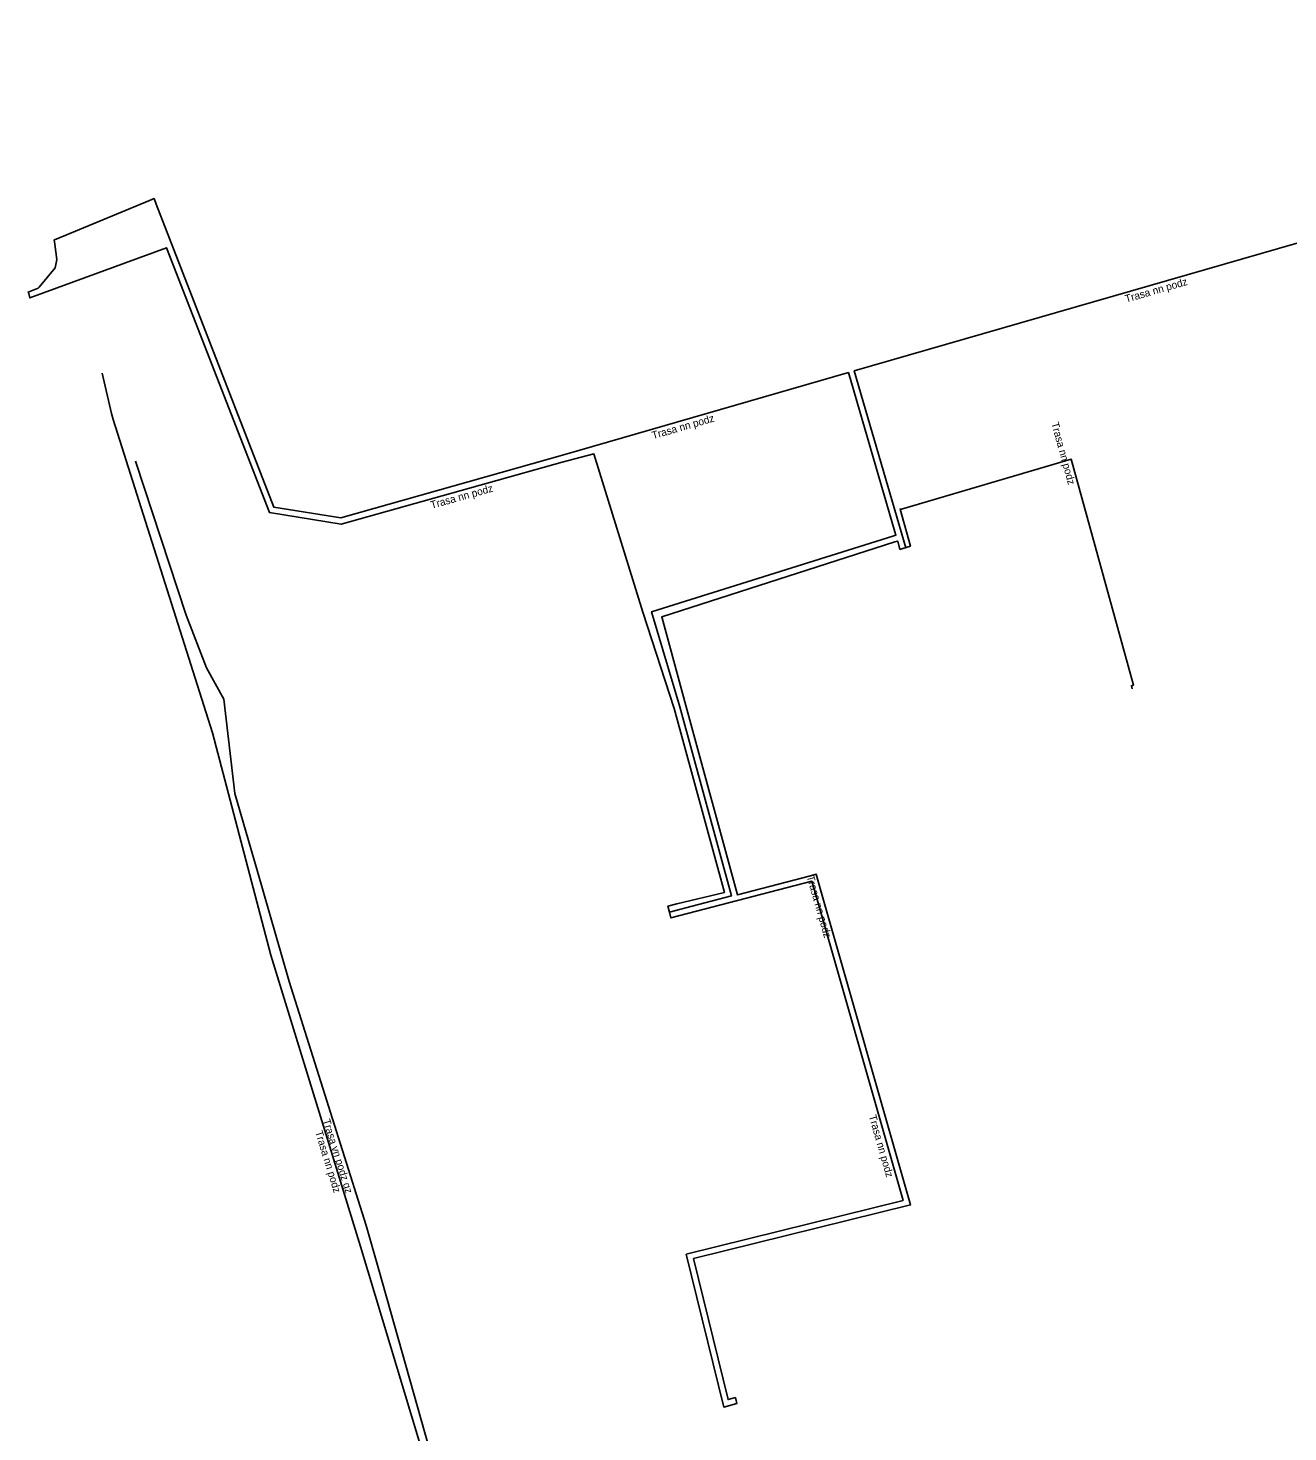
# Model space of a CAD drawing. Extents: x -690200 to -689130, y -975255 to -974631.
# Drawn here: x -689693.2 to -689609.7, y -974998.1 to -974905 of the extents above; entities that cross this region are included whole.
import ezdxf

# ---------------------------------------------------------------- set-up
doc = ezdxf.new("R2010")
doc.units = 0
for name, color, linetype in [('Popiskový text - Ostatní atributy Trasy', 7, 'Continuous'), ('Spojnice NN', 7, 'Continuous'), ('Spojnice VN', 7, 'Continuous')]:
    doc.layers.add(name, color=color, linetype=linetype)

msp = doc.modelspace()

# ---------------------------------------------------------------- linework, layer by layer
at = {"layer": 'Spojnice NN'}
for points in [[(-689599.02, -974905.01), (-689598.965, -974905.202), (-689598.613, -974905.101), (-689595.635, -974915.37), (-689638.473, -974927.736), (-689635.06, -974939.45), (-689635.252, -974939.506)], [(-689693.2, -974922.61), (-689693.242, -974922.509), (-689692.679, -974922.295), (-689692.583, -974922.259), (-689692.515, -974922.178), (-689691.444, -974920.905), (-689691.336, -974920.341), (-689691.473, -974919.336), (-689691.512, -974919.049), (-689691.382, -974918.995), (-689685.197, -974916.44), (-689684.892, -974916.314), (-689684.748, -974916.685), (-689676.953, -974936.764), (-689672.508, -974937.476), (-689657.657, -974933.274), (-689638.857, -974927.847), (-689635.782, -974938.403), (-689635.718, -974938.623), (-689635.91, -974938.683), (-689651.91, -974943.697), (-689650.028, -974950.009), (-689646.614, -974962.533), (-689649.632, -974963.319), (-689650.731, -974963.605)], [(-689693.2, -974922.61), (-689693.127, -974922.892), (-689684.059, -974919.569), (-689677.243, -974937.122), (-689672.49, -974937.884), (-689657.844, -974933.773), (-689655.736, -974933.233), (-689652.497, -974943.725), (-689650.414, -974950.114), (-689647.082, -974962.308), (-689650.238, -974963.063), (-689650.832, -974963.218), (-689650.731, -974963.605)], [(-689658.68, -975032.574), (-689658.299, -975032.453), (-689658.252, -975032.6), (-689657.082, -975032.28), (-689658.52, -975027.184), (-689660.019, -975022.218), (-689661.744, -975017.495), (-689665.364, -975005.112), (-689668.282, -974995.433), (-689671.2, -974985.775), (-689677.143, -974966.45), (-689681.022, -974951.73), (-689687.599, -974930.945), (-689687.722, -974930.557), (-689688.33, -974927.89)], [(-689620.047, -974948.795), (-689620.102, -974948.603), (-689619.968, -974948.565), (-689624.089, -974933.592), (-689635.353, -974936.889), (-689635.435, -974936.893), (-689634.757, -974939.355), (-689635.252, -974939.506)], [(-689646.313, -974995.98), (-689646.355, -974995.783), (-689646.84, -974995.911), (-689649.124, -974986.57), (-689634.738, -974983.013), (-689640.684, -974962.194), (-689640.998, -974961.095), (-689641.365, -974961.189), (-689646.216, -974962.464), (-689649.642, -974949.904), (-689651.24, -974944.033), (-689635.79, -974939.065), (-689635.606, -974939.007), (-689635.574, -974939.116), (-689635.444, -974939.562), (-689635.252, -974939.506)], [(-689650.731, -974963.605), (-689650.63, -974963.992), (-689649.531, -974963.706), (-689641.281, -974961.559), (-689641.068, -974962.304), (-689635.236, -974982.725), (-689649.608, -974986.278), (-689647.13, -974996.41), (-689646.265, -974996.175), (-689646.313, -974995.98)]]:
    msp.add_lwpolyline(points, dxfattribs=at)
at = {"layer": 'Spojnice VN'}
msp.add_lwpolyline([(-689658.41, -975027.96), (-689657.77, -975027.37), (-689659.94, -975021.14), (-689661.47, -975017.42), (-689663.06, -975011.75), (-689664.86, -975005.47), (-689670, -974987.311), (-689670.83, -974984.38), (-689675.93, -974968.21), (-689678.07, -974960.76), (-689679.53, -974955.75), (-689680.26, -974949.49), (-689681.42, -974947.42), (-689682.76, -974943.93), (-689686.12, -974933.72)], dxfattribs=at)

# ---------------------------------------------------------------- texts
at = {"layer": 'Popiskový text - Ostatní atributy Trasy'}
for s, rotation, p in [('Trasa nn podz', 16.10179, (-689620.447, -974923.209)), ('Trasa nn podz', 16.10185, (-689651.813, -974932.263)), ('Trasa nn podz', 285.38844, (-689625.421, -974931.202)), ('Trasa nn podz', 15.67895, (-689666.489, -974936.874)), ('Trasa nn podz', 285.93958, (-689641.631, -974961.244)), ('Trasa nn podz', 285.93873, (-689637.514, -974977.117)), ('Trasa nn podz', 287.09419, (-689674.217, -974978.175)), ('Trasa vn podz gz', 287.50522, (-689673.713, -974977.402))]:
    msp.add_text(s, height=0.5, rotation=rotation, dxfattribs=at).set_placement(p)

doc.saveas('drawing.dxf')
